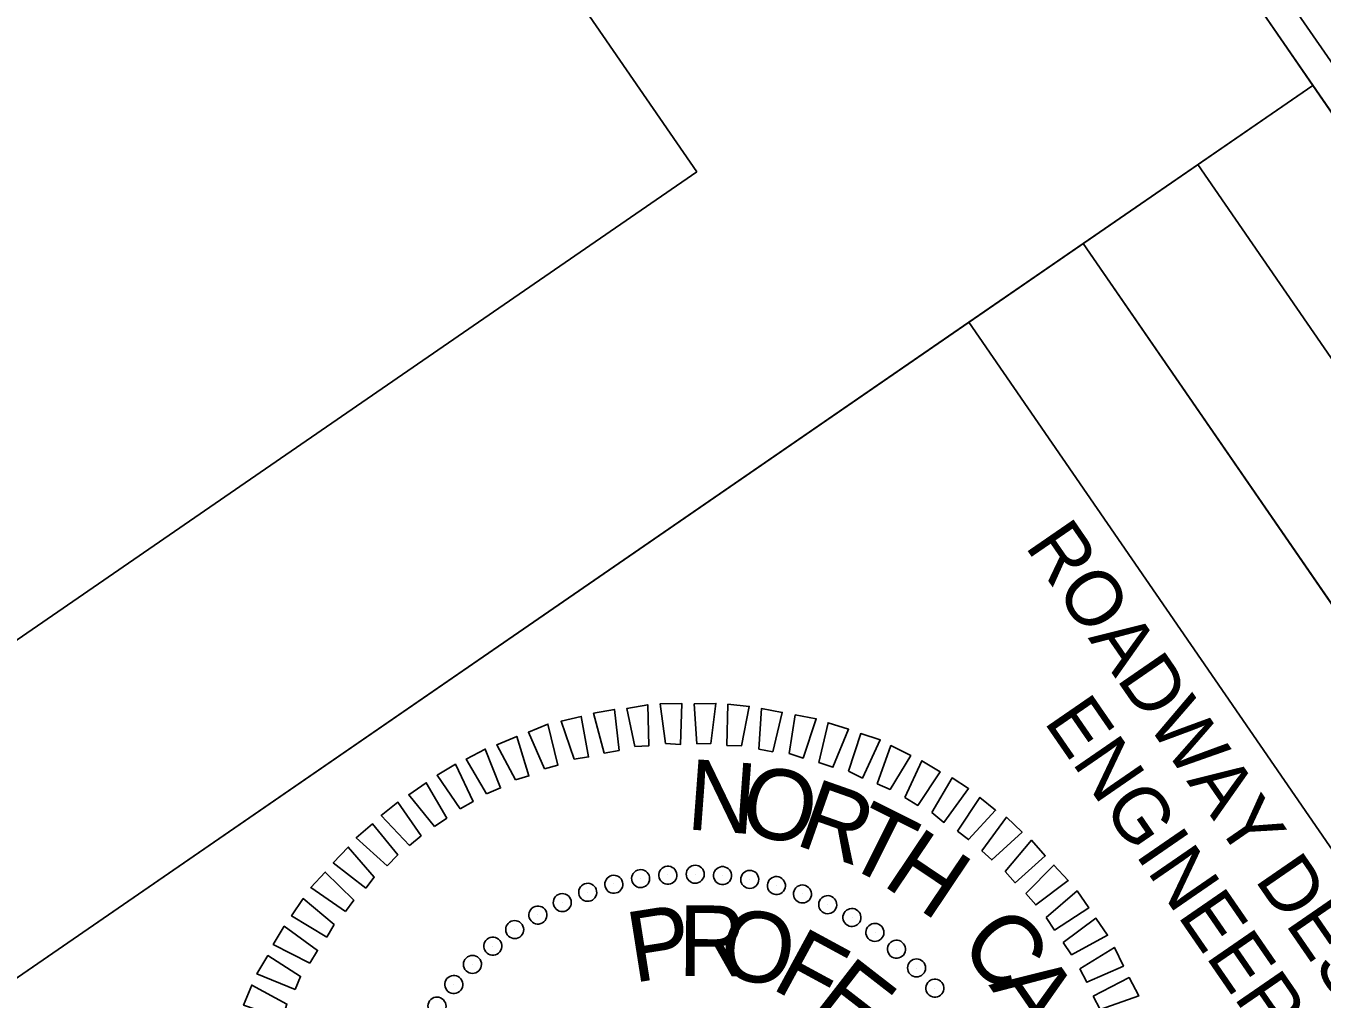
# Model space of a CAD drawing. Extents: x 2297526 to 2298642, y 599613 to 600819.
# Drawn here: x 2298486.8 to 2298556.7, y 600036.6 to 600089.1 of the extents above; entities that cross this region are included whole.
import ezdxf

# ---------------------------------------------------------------- set-up
doc = ezdxf.new("R2010")
doc.units = 0
for name, color, linetype in [('Default', 7, 'Continuous'), ('Exist DTM Drainline Cogo Comment', 7, 'Continuous'), ('Exist DTM Drainline Cogo Elevation', 7, 'Continuous'), ('Exist Property Iron Pin Cogo Number', 7, 'Continuous'), ('Exist Roads Curbs Cogo Number', 7, 'Continuous'), ('Exist Roads Soil Cogo Point CELL', 7, 'Continuous')]:
    doc.layers.add(name, color=color, linetype=linetype)

# ---------------------------------------------------------------- blocks, each defined once
blk = doc.blocks.new('POINT_DISPLAY')
at = {"layer": 'Default'}
blk.add_line((0, 0), (0, 0), dxfattribs=at)

msp = doc.modelspace()

# ---------------------------------------------------------------- linework, layer by layer
at = {"layer": 'Exist DTM Drainline Cogo Comment'}
msp.add_lwpolyline([(2298629.799, 599981.758), (2298062.672, 600805.267), (2297541.289, 600446.206), (2298108.416, 599622.697)], close=True, dxfattribs=at)
at = {"layer": 'Exist DTM Drainline Cogo Elevation'}
for p, q in [((2298550.004, 600081.652), (2298618.083, 599982.796)), ((2298543.827, 600077.398), (2298537.65, 600073.144)), ((2298543.827, 600077.398), (2298611.906, 599978.542)), ((2298543.827, 600077.398), (2298611.906, 599978.542))]:
    msp.add_line(p, q, dxfattribs=at)
for points in [[(2298624.285, 599987.067), (2298113.82, 600728.299), (2297594.957, 600370.974), (2298105.422, 599629.742)], [(2298556.206, 600085.923), (2298624.285, 599987.067), (2298611.906, 599978.542), (2298543.827, 600077.398)], [(2298537.65, 600073.144), (2298571.698, 600023.704), (2298516.106, 599985.419), (2298482.058, 600034.859)]]:
    msp.add_lwpolyline(points, close=True, dxfattribs=at)
at = {"layer": 'Exist Property Iron Pin Cogo Number'}
msp.add_lwpolyline([(2297647.429, 600347.7), (2298036.322, 599783), (2298066.135, 599803.531), (2298144.602, 599689.591), (2298480.39, 599975.839), (2298444.848, 600027.447), (2298522.991, 600081.262), (2298287.234, 600423.597), (2298114.333, 600674.662)], close=True, dxfattribs=at)
at = {"layer": 'Exist Roads Curbs Cogo Number'}
msp.add_lwpolyline([(2298113.82, 600728.299), (2297594.978, 600370.97), (2298105.443, 599629.738), (2298525.543, 599919.075), (2298457.474, 600017.929), (2298556.206, 600085.923)], close=True, dxfattribs=at)
at = {"layer": 'Exist Roads Soil Cogo Point CELL'}
for points in [[(2298519.637, 600050.263), (2298519.213, 600052.307), (2298520.343, 600052.511), (2298520.395, 600050.293)], [(2298521.292, 600050.418), (2298521.007, 600052.559), (2298522.177, 600052.585), (2298522.107, 600050.365)], [(2298522.987, 600050.398), (2298522.851, 600052.559), (2298524.022, 600052.586), (2298523.744, 600050.427)], [(2298524.599, 600050.319), (2298524.669, 600052.539), (2298525.813, 600052.425), (2298525.396, 600050.293)], [(2298526.335, 600050.12), (2298526.47, 600052.304), (2298527.596, 600052.096), (2298527.085, 600049.982)], [(2298516.38, 600049.577), (2298515.665, 600051.626), (2298516.757, 600051.886), (2298517.154, 600049.701)], [(2298517.995, 600049.91), (2298517.419, 600052.055), (2298518.548, 600052.26), (2298518.798, 600050.053)], [(2298527.967, 600049.892), (2298528.3, 600051.966), (2298529.427, 600051.759), (2298528.72, 600049.633)], [(2298514.777, 600049.048), (2298513.904, 600051.028), (2298514.956, 600051.466), (2298515.495, 600049.254)], [(2298529.574, 600049.401), (2298530.068, 600051.544), (2298531.168, 600051.194), (2298530.328, 600049.141)], [(2298531.165, 600048.938), (2298531.827, 600050.953), (2298532.881, 600050.612), (2298531.92, 600048.557)], [(2298513.212, 600048.461), (2298512.201, 600050.347), (2298513.28, 600050.804), (2298513.93, 600048.67)], [(2298532.711, 600048.24), (2298533.457, 600050.311), (2298534.523, 600049.775), (2298533.408, 600047.943)], [(2298511.641, 600047.708), (2298510.555, 600049.582), (2298511.577, 600050.123), (2298512.405, 600048.029)], [(2298510.231, 600046.899), (2298508.986, 600048.707), (2298509.97, 600049.301), (2298510.936, 600047.303)], [(2298534.201, 600047.505), (2298535.126, 600049.494), (2298536.109, 600048.901), (2298534.901, 600047.085)], [(2298508.841, 600045.942), (2298507.457, 600047.654), (2298508.402, 600048.304), (2298509.507, 600046.401)], [(2298535.656, 600046.703), (2298536.751, 600048.564), (2298537.64, 600047.988), (2298536.309, 600046.169)], [(2298537.047, 600045.693), (2298538.255, 600047.51), (2298539.099, 600046.82), (2298537.643, 600045.244)], [(2298507.489, 600044.929), (2298505.967, 600046.545), (2298506.873, 600047.251), (2298508.117, 600045.444)], [(2298506.288, 600043.816), (2298504.627, 600045.336), (2298505.495, 600046.098), (2298506.859, 600044.415)], [(2298538.355, 600044.627), (2298539.685, 600046.445), (2298540.531, 600045.634), (2298538.896, 600044.14)], [(2298505.144, 600042.619), (2298503.383, 600043.987), (2298504.194, 600044.833), (2298505.596, 600043.215)], [(2298539.608, 600043.523), (2298541.033, 600045.202), (2298541.778, 600044.36), (2298540.151, 600042.912)], [(2298504.04, 600041.366), (2298502.168, 600042.658), (2298502.951, 600043.485), (2298504.491, 600041.963)], [(2298540.722, 600042.323), (2298542.244, 600043.862), (2298543.014, 600043.04), (2298541.265, 600041.713)], [(2298503.031, 600039.974), (2298501.132, 600041.125), (2298501.765, 600042.053), (2298503.424, 600040.654)], [(2298541.818, 600041.029), (2298543.491, 600042.467), (2298544.123, 600041.55), (2298542.278, 600040.361)], [(2298502.117, 600038.565), (2298500.144, 600039.585), (2298500.739, 600040.567), (2298502.536, 600039.264)], [(2298542.738, 600039.693), (2298544.506, 600040.994), (2298545.138, 600040.076), (2298543.197, 600039.027)], [(2298543.639, 600038.265), (2298545.503, 600039.426), (2298545.996, 600038.413), (2298544.015, 600037.541)], [(2298501.323, 600037.158), (2298499.269, 600037.998), (2298499.862, 600038.981), (2298501.621, 600037.856)], [(2298544.363, 600036.796), (2298546.296, 600037.8), (2298546.816, 600036.806), (2298544.739, 600036.072)], [(2298500.645, 600035.584), (2298498.546, 600036.311), (2298498.988, 600037.394), (2298500.886, 600036.365)]]:
    msp.add_lwpolyline(points, close=True, dxfattribs=at)
for centre, major_axis in [((2298518.516, 600042.829), (-0.122, 0.47)), ((2298519.96, 600043.137), (-0.081, 0.479)), ((2298521.426, 600043.319), (-0.039, 0.485)), ((2298522.902, 600043.371), (0.004, 0.486)), ((2298524.378, 600043.296), (0.046, 0.484)), ((2298525.841, 600043.091), (0.088, 0.478)), ((2298527.28, 600042.76), (0.129, 0.469)), ((2298517.103, 600042.395), (-0.163, 0.458)), ((2298528.685, 600042.305), (0.17, 0.455)), ((2298515.734, 600041.841), (-0.202, 0.442)), ((2298530.046, 600041.729), (0.209, 0.439)), ((2298514.419, 600041.169), (-0.24, 0.423)), ((2298531.351, 600041.037), (0.246, 0.419)), ((2298513.167, 600040.385), (-0.276, 0.4)), ((2298532.59, 600040.234), (0.282, 0.396)), ((2298511.988, 600039.495), (-0.31, 0.375)), ((2298533.755, 600039.326), (0.315, 0.37)), ((2298510.891, 600038.505), (-0.341, 0.346)), ((2298534.836, 600038.319), (0.346, 0.341)), ((2298509.885, 600037.424), (-0.37, 0.315)), ((2298535.826, 600037.222), (0.375, 0.31)), ((2298508.977, 600036.259), (-0.396, 0.282))]:
    msp.add_ellipse(centre, major_axis=major_axis, ratio=0.999708, dxfattribs=at)

# ---------------------------------------------------------------- block references
at = {"layer": 'Exist Roads Soil Cogo Point CELL', "xscale": 41.411959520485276, "yscale": 41.41195952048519, "rotation": -55.44551104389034}
for p in [(2298521.418, 600043.332), (2298522.906, 600043.374), (2298524.377, 600043.321), (2298518.512, 600042.848), (2298519.95, 600043.141), (2298525.841, 600043.1), (2298527.288, 600042.784), (2298515.728, 600041.833), (2298517.097, 600042.406), (2298528.681, 600042.309), (2298514.418, 600041.176), (2298530.056, 600041.741), (2298531.359, 600041.039), (2298513.157, 600040.39), (2298532.597, 600040.252), (2298511.972, 600039.491), (2298533.763, 600039.333), (2298510.891, 600038.502), (2298534.836, 600038.31), (2298509.868, 600037.428), (2298535.827, 600037.23)]:
    msp.add_blockref('POINT_DISPLAY', p, dxfattribs=at)

# ---------------------------------------------------------------- texts
at = {"layer": 'Exist DTM Drainline Cogo Elevation'}
for s, height, p in [('ROADWAY DESIGN', 3.00007, (2298540.645, 600061.073)), ('ENGINEER', 3.0001, (2298541.661, 600051.61))]:
    msp.add_text(s, height=height, rotation=304.55406, dxfattribs=at).set_placement(p)
at = {"layer": 'Exist Roads Soil Cogo Point CELL'}
for s, height, rotation, p in [('N', 3.806, 355.71496, (2298522.38, 600045.799)), ('O', 3.806, 347.77623, (2298525.137, 600045.68)), ('R', 3.806, 340.57499, (2298528.187, 600044.996)), ('T', 3.806, 333.37426, (2298530.717, 600043.995)), ('H', 3.806, 326.17397, (2298532.906, 600042.84)), ('P', 3.807, 8.95338, (2298519.572, 600037.509)), ('R', 3.807, 359.59414, (2298521.975, 600037.891)), ('O', 3.807, 350.23573, (2298524.018, 600037.902)), ('C', 3.806, 311.77436, (2298536.996, 600039.461)), ('F', 3.807, 331.52152, (2298526.918, 600037.247)), ('E', 3.807, 322.16556, (2298529.006, 600036.061)), ('A', 3.806, 304.57481, (2298538.703, 600037.396))]:
    msp.add_text(s, height=height, rotation=rotation, dxfattribs=at).set_placement(p)

doc.saveas('drawing.dxf')
